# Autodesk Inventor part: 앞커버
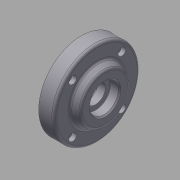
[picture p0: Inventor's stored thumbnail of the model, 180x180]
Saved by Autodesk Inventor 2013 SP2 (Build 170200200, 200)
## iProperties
Company: 한국ATC센터
Created: 2015-12
Part Number: 앞커버
Document SubType Name: Modeling
Designer: 앞커버
Density: 2.71 g/cm^3
Mass: 114.339 g
Surface Area: 117.889 cm^2
Volume: 42.1916 cm^3
Material: 알루미늄-6061
Author: mdu
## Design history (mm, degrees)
sketch "스케치1"
  geometry: L1 (-11.5, 0)-(11.5, 0); L2 (11.5, 0)-(11.5, 22.5); L3 (11.5, 22.5)-(6.5, 22.5); L4 (6.5, 22.5)-(6.5, 32.5); L5 (6.5, 32.5)-(-5.5, 32.5); L6 (-5.5, 32.5)-(-5.5, 21); L7 (-5.5, 21)-(-11.5, 18.202); L8 (-11.5, 18.202)-(-11.5, 0); 2 further points
  constraints: 16 end point, 3 parallel, 3 perpendicular, 1 coincident, 1 horizontal, 1 midpoint
  dimensions: "d0" = 23 distance of L1.start L1.end; "d1" = 65 diameter of L5 L1; "d2" = 45 diameter of L3 L1; "d3" = 42 diameter of L6.end L1; "d4" = 115 deg angle of L7 L6; "d5" = 12 distance of L4.end L5.end; "d6" = 5 distance of L2.end L3.end
revolve "회전1" sketch "스케치1" stored, may be unused: angle "d7" = 90 deg
sketch "스케치2"
  geometry: L1 (0, 0)-(32.5, 0); L2 (0, 0)-(18.738, 18.738); 1 further point
  constraints: 4 end point, 1 horizontal, 1 horizontal alignment, 1 other
  dimensions: "d8" = 45 deg angle of L1 L2; "d9" = 26.5 distance of L1.start L2.end
hole "구멍1" sketch "스케치2" at (18.738, 18.738) diameter "d10" = 3.4; stored, may be unused: countersink angle "d14" = 90 deg, drill point angle "d16" = 118 deg; dims "d11" = 6, "d12" = 6, "d13" = 3.3, "d15" = 8
fillet "모깎기1" dims "d20" = 2
hole "구멍2" diameter "d23" = 15; stored, may be unused: countersink angle "d27" = 90 deg, drill point angle "d29" = 118 deg; dims "d21" = 10, "d22" = 10, "d24" = 6, "d25" = 32, "d26" = 10, "d28" = 8
hole "구멍3" diameter "d32" = 22; stored, may be unused: countersink angle "d36" = 90 deg, drill point angle "d38" = 0 deg; dims "d30" = 10, "d31" = 10, "d33" = 6, "d34" = 32, "d35" = 10, "d37" = 7.3
chamfer "모따기1" distance "d39" = 1; stored, may be unused: second distance "d40" = 2, angle "d41" = 45 deg
fillet "모깎기2" dims "d42" = 0.3
node "솔리드1"
pattern_circular "원형 패턴1" dims angle "d18" = 360 deg
